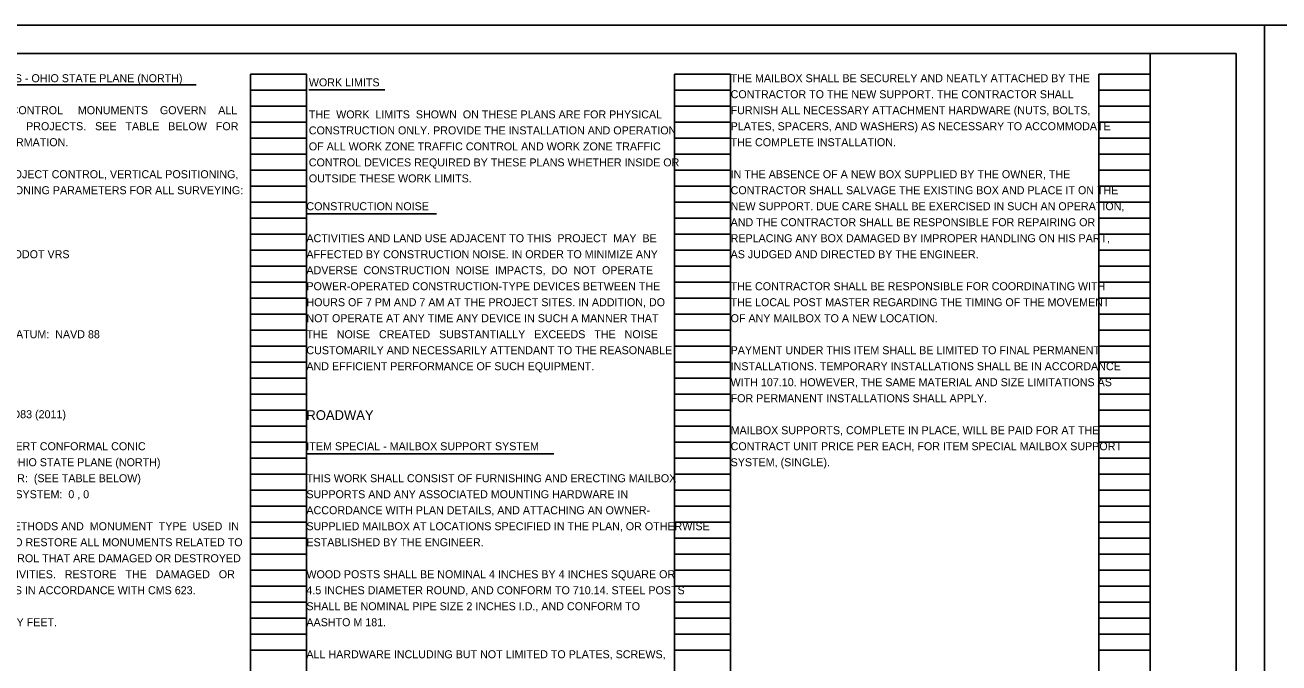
# Model space of a CAD drawing. Extents: x 0 to 102, y 0 to 22.
# Drawn here: x 12.32 to 34.25, y 10.84 to 22 of the extents above; entities that cross this region are included whole.
import ezdxf

# ---------------------------------------------------------------- set-up
doc = ezdxf.new("R2010")
doc.units = 0
doc.layers.add('SC_Scratch1', color=7, linetype='Continuous')
doc.layers.add('SH_Text', color=7, linetype='Continuous')

msp = doc.modelspace()

# ---------------------------------------------------------------- linework, layer by layer
at = {"layer": 'SC_Scratch1'}
for p, q in [((16.26, 0.98), (16.26, 21.14)), ((16.26, 21.14), (17.24, 21.14)), ((17.24, 0.98), (17.24, 21.14)), ((23.68, 0.98), (23.68, 21.14)), ((23.68, 21.14), (24.66, 21.14)), ((24.66, 0.98), (24.66, 21.14)), ((31.1, 0.98), (31.1, 21.14)), ((31.1, 21.14), (32, 21.14)), ((32, 0.98), (32, 21.14)), ((16.26, 20.86), (17.24, 20.86)), ((23.68, 20.86), (24.66, 20.86)), ((31.1, 20.86), (32, 20.86)), ((16.26, 20.58), (17.24, 20.58)), ((23.68, 20.58), (24.66, 20.58)), ((31.1, 20.58), (32, 20.58)), ((16.26, 20.3), (17.24, 20.3)), ((23.68, 20.3), (24.66, 20.3)), ((31.1, 20.3), (32, 20.3)), ((16.26, 20.02), (17.24, 20.02)), ((23.68, 20.02), (24.66, 20.02)), ((31.1, 20.02), (32, 20.02)), ((16.26, 19.74), (17.24, 19.74)), ((23.68, 19.74), (24.66, 19.74)), ((31.1, 19.74), (32, 19.74)), ((16.26, 19.46), (17.24, 19.46)), ((23.68, 19.46), (24.66, 19.46)), ((31.1, 19.46), (32, 19.46)), ((16.26, 19.18), (17.24, 19.18)), ((23.68, 19.18), (24.66, 19.18)), ((31.1, 19.18), (32, 19.18)), ((16.26, 18.9), (17.24, 18.9)), ((23.68, 18.9), (24.66, 18.9)), ((31.1, 18.9), (32, 18.9)), ((16.26, 18.62), (17.24, 18.62)), ((23.68, 18.62), (24.66, 18.62)), ((31.1, 18.62), (32, 18.62)), ((16.26, 18.34), (17.24, 18.34)), ((23.68, 18.34), (24.66, 18.34)), ((31.1, 18.34), (32, 18.34)), ((16.26, 18.06), (17.24, 18.06)), ((23.68, 18.06), (24.66, 18.06)), ((31.1, 18.06), (32, 18.06)), ((16.26, 17.78), (17.24, 17.78)), ((23.68, 17.78), (24.66, 17.78)), ((31.1, 17.78), (32, 17.78)), ((16.26, 17.5), (17.24, 17.5)), ((23.68, 17.5), (24.66, 17.5)), ((31.1, 17.5), (32, 17.5)), ((16.26, 17.22), (17.24, 17.22)), ((23.68, 17.22), (24.66, 17.22)), ((31.1, 17.22), (32, 17.22)), ((16.26, 16.94), (17.24, 16.94)), ((23.68, 16.94), (24.66, 16.94)), ((31.1, 16.94), (32, 16.94)), ((16.26, 16.66), (17.24, 16.66)), ((23.68, 16.66), (24.66, 16.66)), ((31.1, 16.66), (32, 16.66)), ((16.26, 16.38), (17.24, 16.38)), ((23.68, 16.38), (24.66, 16.38)), ((31.1, 16.38), (32, 16.38)), ((16.26, 16.1), (17.24, 16.1)), ((23.68, 16.1), (24.66, 16.1)), ((31.1, 16.1), (32, 16.1)), ((16.26, 15.82), (17.24, 15.82)), ((23.68, 15.82), (24.66, 15.82)), ((31.1, 15.82), (32, 15.82)), ((16.26, 15.54), (17.24, 15.54)), ((23.68, 15.54), (24.66, 15.54)), ((31.1, 15.54), (32, 15.54)), ((16.26, 15.26), (17.24, 15.26)), ((23.68, 15.26), (24.66, 15.26)), ((31.1, 15.26), (32, 15.26)), ((16.26, 14.98), (17.24, 14.98)), ((23.68, 14.98), (24.66, 14.98)), ((31.1, 14.98), (32, 14.98)), ((16.26, 14.7), (17.24, 14.7)), ((23.68, 14.7), (24.66, 14.7)), ((31.1, 14.7), (32, 14.7)), ((16.26, 14.42), (17.24, 14.42)), ((23.68, 14.42), (24.66, 14.42)), ((31.1, 14.42), (32, 14.42)), ((16.26, 14.14), (17.24, 14.14)), ((23.68, 14.14), (24.66, 14.14)), ((31.1, 14.14), (32, 14.14)), ((16.26, 13.86), (17.24, 13.86)), ((23.68, 13.86), (24.66, 13.86)), ((31.1, 13.86), (32, 13.86)), ((16.26, 13.58), (17.24, 13.58)), ((23.68, 13.58), (24.66, 13.58)), ((31.1, 13.58), (32, 13.58)), ((16.26, 13.3), (17.24, 13.3)), ((23.68, 13.3), (24.66, 13.3)), ((31.1, 13.3), (32, 13.3)), ((16.26, 13.02), (17.24, 13.02)), ((23.68, 13.02), (24.66, 13.02)), ((31.1, 13.02), (32, 13.02)), ((16.26, 12.74), (17.24, 12.74)), ((23.68, 12.74), (24.66, 12.74)), ((31.1, 12.74), (32, 12.74)), ((16.26, 12.46), (17.24, 12.46)), ((23.68, 12.46), (24.66, 12.46)), ((31.1, 12.46), (32, 12.46)), ((16.26, 12.18), (17.24, 12.18)), ((23.68, 12.18), (24.66, 12.18)), ((31.1, 12.18), (32, 12.18)), ((16.26, 11.9), (17.24, 11.9)), ((23.68, 11.9), (24.66, 11.9)), ((31.1, 11.9), (32, 11.9)), ((16.26, 11.62), (17.24, 11.62)), ((23.68, 11.62), (24.66, 11.62)), ((31.1, 11.62), (32, 11.62)), ((16.26, 11.34), (17.24, 11.34)), ((23.68, 11.34), (24.66, 11.34)), ((31.1, 11.34), (32, 11.34)), ((16.26, 11.06), (17.24, 11.06)), ((23.68, 11.06), (24.66, 11.06)), ((31.1, 11.06), (32, 11.06))]:
    msp.add_line(p, q, dxfattribs=at)
for points in [[(0, 22), (34, 22), (34, 0), (0, 0)], [(34, 22), (68, 22), (68, 0), (34, 0)], [(0.5, 21.5), (33.5, 21.5), (33.5, 0.5), (0.5, 0.5)], [(1.5, 21.5), (32, 21.5), (32, 0.5), (1.5, 0.5)]]:
    msp.add_lwpolyline(points, close=True, dxfattribs=at)
at = {"layer": 'SH_Text'}
for p, q in [((9.82, 20.953), (15.311, 20.953)), ((17.282, 20.866), (18.614, 20.866)), ((17.24, 18.699), (19.517, 18.699)), ((17.24, 14.499), (21.565, 14.499))]:
    msp.add_line(p, q, dxfattribs=at)

# ---------------------------------------------------------------- texts
for s, height, p in [('SURVEYING PARAMETERS - OHIO STATE PLANE (NORTH)', 0.14, (9.82, 21)), ('WORK LIMITS', 0.14, (17.282, 20.927)), ('THE MAILBOX SHALL BE SECURELY AND NEATLY ATTACHED BY THE', 0.14, (24.66, 21)), ('CONTRACTOR TO THE NEW SUPPORT. THE CONTRACTOR SHALL', 0.14, (24.66, 20.72)), ('PRIMARY     PROJECT     CONTROL     MONUMENTS    GOVERN    ALL', 0.14, (9.82, 20.44)), ('THE  WORK  LIMITS  SHOWN  ON THESE PLANS ARE FOR PHYSICAL', 0.14, (17.282, 20.367)), ('FURNISH ALL NECESSARY ATTACHMENT HARDWARE (NUTS, BOLTS,', 0.14, (24.66, 20.44)), ('POSITIONING   ON   ODOT   PROJECTS.   SEE   TABLE   BELOW   FOR', 0.14, (9.82, 20.16)), ('CONSTRUCTION ONLY. PROVIDE THE INSTALLATION AND OPERATION', 0.14, (17.282, 20.087)), ('PLATES, SPACERS, AND WASHERS) AS NECESSARY TO ACCOMMODATE', 0.14, (24.66, 20.16)), ('PROJECT CONTROL INFORMATION.', 0.14, (9.82, 19.88)), ('THE COMPLETE INSTALLATION.', 0.14, (24.66, 19.88)), ('OF ALL WORK ZONE TRAFFIC CONTROL AND WORK ZONE TRAFFIC', 0.14, (17.282, 19.807)), ('CONTROL DEVICES REQUIRED BY THESE PLANS WHETHER INSIDE OR', 0.14, (17.282, 19.527)), ('USE THE FOLLOWING PROJECT CONTROL, VERTICAL POSITIONING,', 0.14, (9.82, 19.32)), ('OUTSIDE THESE WORK LIMITS.', 0.14, (17.282, 19.247)), ('IN THE ABSENCE OF A NEW BOX SUPPLIED BY THE OWNER, THE', 0.14, (24.66, 19.32)), ('AND HORIZONTAL POSITIONING PARAMETERS FOR ALL SURVEYING:', 0.14, (9.82, 19.04)), ('CONTRACTOR SHALL SALVAGE THE EXISTING BOX AND PLACE IT ON THE', 0.14, (24.66, 19.04)), ('CONSTRUCTION NOISE', 0.14, (17.24, 18.76)), ('NEW SUPPORT. DUE CARE SHALL BE EXERCISED IN SUCH AN OPERATION,', 0.14, (24.66, 18.76)), ('AND THE CONTRACTOR SHALL BE RESPONSIBLE FOR REPAIRING OR', 0.14, (24.66, 18.48)), ('ACTIVITIES AND LAND USE ADJACENT TO THIS  PROJECT  MAY  BE', 0.14, (17.24, 18.2)), ('REPLACING ANY BOX DAMAGED BY IMPROPER HANDLING ON HIS PART,', 0.14, (24.66, 18.2)), ('POSITIONING  METHOD:  ODOT VRS', 0.14, (9.82, 17.92)), ('AFFECTED BY CONSTRUCTION NOISE. IN ORDER TO MINIMIZE ANY', 0.14, (17.24, 17.92)), ('AS JUDGED AND DIRECTED BY THE ENGINEER.', 0.14, (24.66, 17.92)), ('ADVERSE  CONSTRUCTION  NOISE  IMPACTS,  DO  NOT  OPERATE', 0.14, (17.24, 17.64)), ('POWER-OPERATED CONSTRUCTION-TYPE DEVICES BETWEEN THE', 0.14, (17.24, 17.36)), ('THE CONTRACTOR SHALL BE RESPONSIBLE FOR COORDINATING WITH', 0.14, (24.66, 17.36)), ('HOURS OF 7 PM AND 7 AM AT THE PROJECT SITES. IN ADDITION, DO', 0.14, (17.24, 17.08)), ('THE LOCAL POST MASTER REGARDING THE TIMING OF THE MOVEMENT', 0.14, (24.66, 17.08)), ('NOT OPERATE AT ANY TIME ANY DEVICE IN SUCH A MANNER THAT', 0.14, (17.24, 16.8)), ('OF ANY MAILBOX TO A NEW LOCATION.', 0.14, (24.66, 16.8)), ('ORTHOMETRIC HEIGHT DATUM:  NAVD 88', 0.14, (9.82, 16.52)), ('THE   NOISE   CREATED   SUBSTANTIALLY   EXCEEDS   THE   NOISE', 0.14, (17.24, 16.52)), ('CUSTOMARILY AND NECESSARILY ATTENDANT TO THE REASONABLE', 0.14, (17.24, 16.24)), ('PAYMENT UNDER THIS ITEM SHALL BE LIMITED TO FINAL PERMANENT', 0.14, (24.66, 16.24)), ('AND EFFICIENT PERFORMANCE OF SUCH EQUIPMENT.', 0.14, (17.24, 15.96)), ('INSTALLATIONS. TEMPORARY INSTALLATIONS SHALL BE IN ACCORDANCE', 0.14, (24.66, 15.96)), ('WITH 107.10. HOWEVER, THE SAME MATERIAL AND SIZE LIMITATIONS AS', 0.14, (24.66, 15.68)), ('FOR PERMANENT INSTALLATIONS SHALL APPLY.', 0.14, (24.66, 15.4)), ('REFERENCE FRAME:  NAD83 (2011)', 0.14, (9.82, 15.12)), ('ROADWAY', 0.17, (17.24, 15.09)), ('MAILBOX SUPPORTS, COMPLETE IN PLACE, WILL BE PAID FOR AT THE', 0.14, (24.66, 14.84)), ('MAP PROJECTION:  LAMBERT CONFORMAL CONIC', 0.14, (9.82, 14.56)), ('ITEM SPECIAL - MAILBOX SUPPORT SYSTEM', 0.14, (17.24, 14.56)), ('CONTRACT UNIT PRICE PER EACH, FOR ITEM SPECIAL MAILBOX SUPPORT', 0.14, (24.66, 14.56)), ('COORDINATE SYSTEM:  OHIO STATE PLANE (NORTH)', 0.14, (9.82, 14.28)), ('SYSTEM, (SINGLE).', 0.14, (24.66, 14.28)), ('COMBINED SCALE FACTOR:  (SEE TABLE BELOW)', 0.14, (9.82, 14)), ('THIS WORK SHALL CONSIST OF FURNISHING AND ERECTING MAILBOX', 0.14, (17.24, 14)), ('ORIGIN OF COORDINATE SYSTEM:  0 , 0', 0.14, (9.82, 13.72)), ('SUPPORTS AND ANY ASSOCIATED MOUNTING HARDWARE IN', 0.14, (17.24, 13.72)), ('ACCORDANCE WITH PLAN DETAILS, AND ATTACHING AN OWNER-', 0.14, (17.24, 13.44)), ('USE THE POSITIONING METHODS AND  MONUMENT  TYPE  USED  IN', 0.14, (9.82, 13.16)), ('SUPPLIED MAILBOX AT LOCATIONS SPECIFIED IN THE PLAN, OR OTHERWISE', 0.14, (17.24, 13.16)), ('THE ORIGINAL SURVEY TO RESTORE ALL MONUMENTS RELATED TO', 0.14, (9.82, 12.88)), ('ESTABLISHED BY THE ENGINEER.', 0.14, (17.24, 12.88)), ('PRIMARY PROJECT CONTROL THAT ARE DAMAGED OR DESTROYED', 0.14, (9.82, 12.6)), ('BY  CONSTRUCTION  ACTIVITIES.   RESTORE   THE   DAMAGED   OR', 0.14, (9.82, 12.32)), ('WOOD POSTS SHALL BE NOMINAL 4 INCHES BY 4 INCHES SQUARE OR', 0.14, (17.24, 12.32)), ('DESTROYED MONUMENTS IN ACCORDANCE WITH CMS 623.', 0.14, (9.82, 12.04)), ('4.5 INCHES DIAMETER ROUND, AND CONFORM TO 710.14. STEEL POSTS ', 0.14, (17.24, 12.04)), ('SHALL BE NOMINAL PIPE SIZE 2 INCHES I.D., AND CONFORM TO', 0.14, (17.24, 11.76)), ('UNITS ARE IN U.S. SURVEY FEET.', 0.14, (9.82, 11.48)), ('AASHTO M 181.', 0.14, (17.24, 11.48)), ('ALL HARDWARE INCLUDING BUT NOT LIMITED TO PLATES, SCREWS,', 0.14, (17.24, 10.92))]:
    msp.add_text(s, height=height, dxfattribs=at).set_placement(p)

doc.saveas('drawing.dxf')
